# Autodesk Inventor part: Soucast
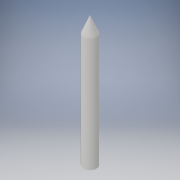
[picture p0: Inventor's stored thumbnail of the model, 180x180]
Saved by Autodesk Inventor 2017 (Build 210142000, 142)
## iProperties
Part Number: Soucast
Material: Všeobecné
Document SubType Name: Modeling
Designer: Polesny
Mass: 7.22194 g
Surface Area: 30.4614 cm^2
Volume: 7.22194 cm^3
Density: 1 g/cm^3
Appearance: Výchozí
Author: Polesny
Mass: 0,007
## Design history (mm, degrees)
sketch "Náčrt1"
  geometry: L1 (0, 0)-(100, 0); L2 (100, 0)-(87.929, 5); L3 (87.929, 5)-(0, 5); L4 (0, 5)-(0, 0)
  constraints: 8 end point, 1 horizontal, 1 parallel, 1 perpendicular
  dimensions: "d0" = 10 diameter of L3 L1; "d1" = 100 distance from line of L4 L1.end; "d2" = 22.5 deg angle of L1 L2
revolve "Rotace1" sketch "Náčrt1" stored, may be unused: angle "d3" = 90 deg
node "Těleso1"
